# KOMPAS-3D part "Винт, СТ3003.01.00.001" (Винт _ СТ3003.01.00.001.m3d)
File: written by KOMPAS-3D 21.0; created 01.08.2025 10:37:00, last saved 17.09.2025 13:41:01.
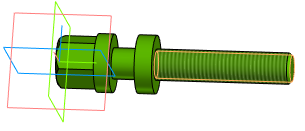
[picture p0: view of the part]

Document properties: Полное имя файла: C:\Users\1\Yandex.Disk\Документы\Новая папка\Стапель №2\Стапель _ СТ3003.00.00.000\Опора _ СТ3003.01.00.000\3D\Винт _ СТ3003.01.00.001.m3d; Автор: 1

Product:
- Part/product: Винт  | designation СТ3003.01.00.001
    Материал: Круг$d30 ГОСТ 2590-2006;Ст3сп ГОСТ 535-2005$ (density 7850 kg/m3)
    Масса: 0.303608
    Форматы листов документа: A4
    additional columns: 120

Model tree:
1. Эскиз:1
2. Элемент выдавливания:1
3. Эскиз:2
4. Элемент вращения:1
     Угол 1 = 360
5. Условное изображение резьбы:1  (with: Элемент вращения:1)  (labels: M16; cil0_24705-2004 coarse)
     Длина резьбы = 70; Шаг резьбы = 2; Номинальный диаметр резьбы = 16
6. Подгонка:1  (with: Элемент вращения:1)
7. Фаска:1  (with: Элемент вращения:1)
     Угол = 45; Длина 1 = 1.6; Длина 2 = 1.6
8. Эскиз:3  (with: Элемент выдавливания:1)
9. Элемент выдавливания:2
     Толщина стенки 1 = 8; Расстояние 2 = 20
10. Эскиз:4  (with: Элемент выдавливания:2)
11. Элемент вращения:2  (labels: Круг$d30 ГОСТ 2590-2006;Ст3сп ГОСТ 535-2005$)
     Угол 1 = 360

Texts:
  СТ3003.01.00.001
